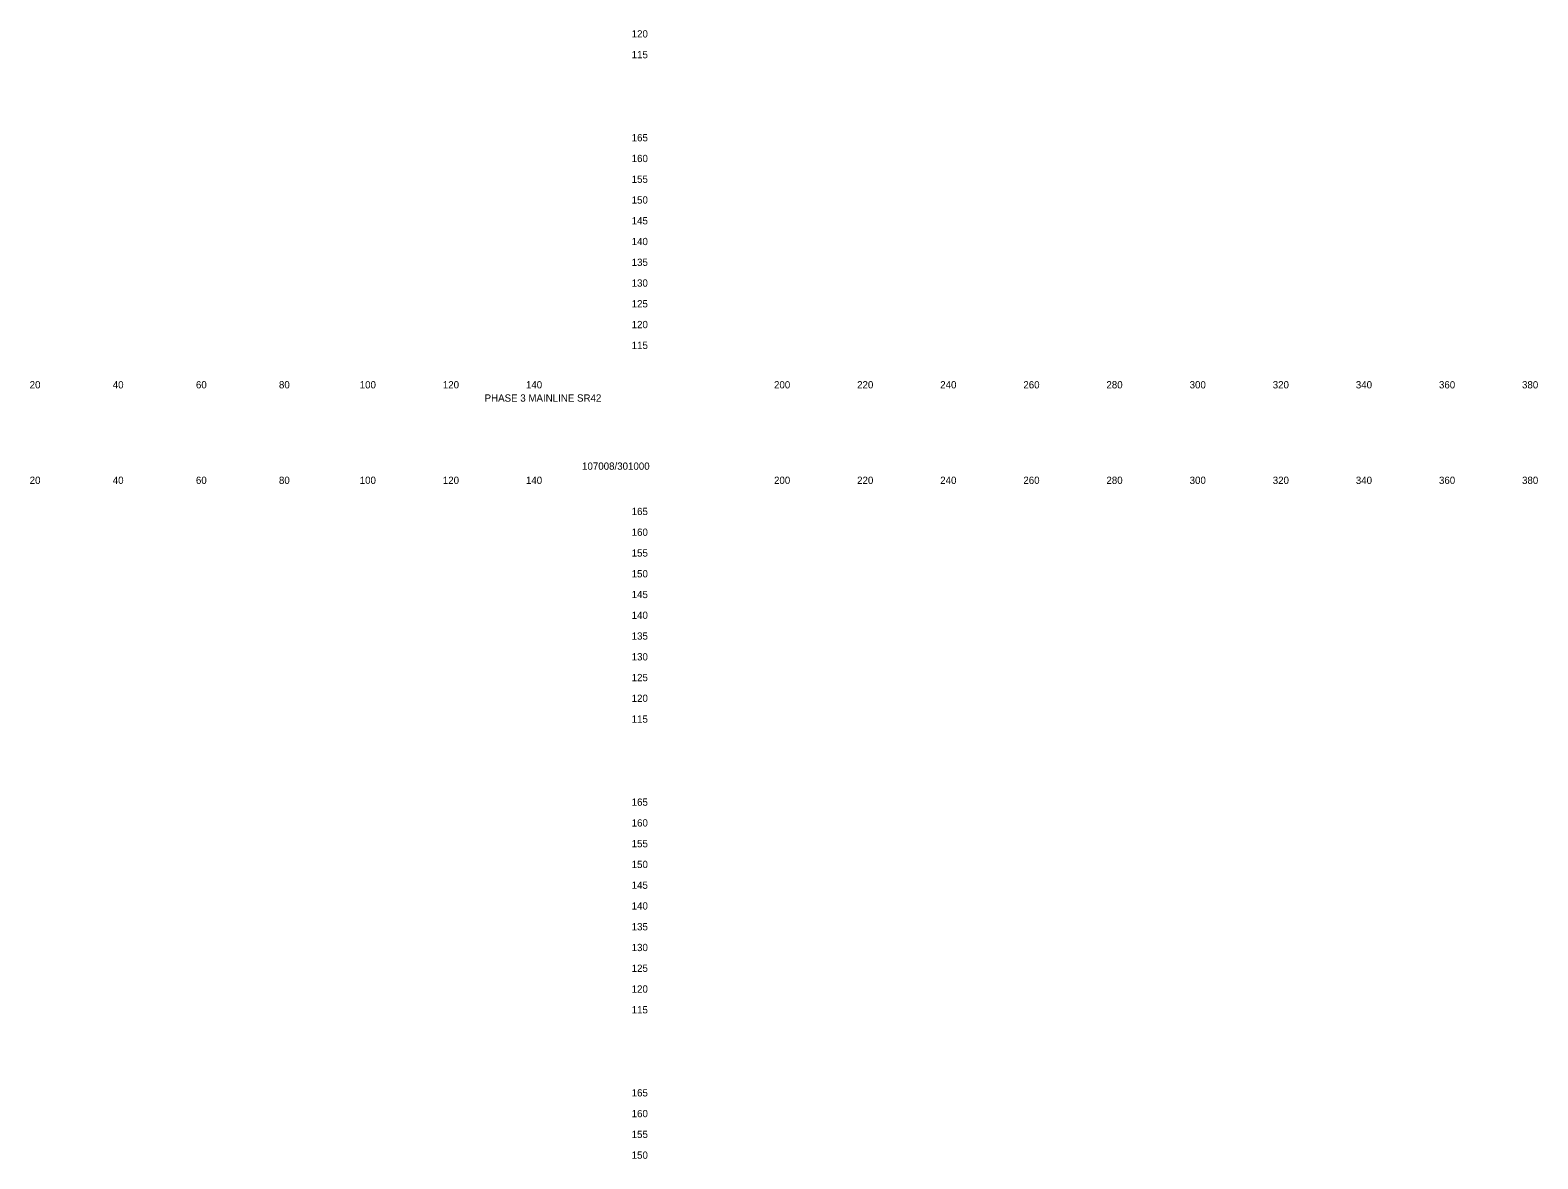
# Model space of a CAD drawing. Extents: x 21281 to 22024, y 6472 to 15198.
# Drawn here: x 21661.4 to 22024.2, y 14109.8 to 14381.6 of the extents above; entities that cross this region are included whole.
import ezdxf

# ---------------------------------------------------------------- set-up
doc = ezdxf.new("R2010")
doc.units = 0
doc.layers.add('Draft_XS_Grid', color=7, linetype='Continuous')
doc.layers.add('Draft_XS_Text', color=7, linetype='Continuous')

msp = doc.modelspace()

# ---------------------------------------------------------------- texts
at = {"layer": 'Draft_XS_Grid'}
for s, p in [('  120  ', (21804.84, 14379.84)), ('  115  ', (21804.84, 14374.84)), ('  165  ', (21804.84, 14354.84)), ('  160  ', (21804.84, 14349.84)), ('  155  ', (21804.84, 14344.84)), ('  150  ', (21804.84, 14339.84)), ('  145  ', (21804.84, 14334.84)), ('  140  ', (21804.84, 14329.84)), ('  135  ', (21804.84, 14324.84)), ('  130  ', (21804.84, 14319.84)), ('  125  ', (21804.84, 14314.84)), ('  120  ', (21804.84, 14309.84)), ('  115  ', (21804.84, 14304.84)), ('  165  ', (21804.84, 14264.84)), ('  160  ', (21804.84, 14259.84)), ('  155  ', (21804.84, 14254.84)), ('  150  ', (21804.84, 14249.84)), ('  145  ', (21804.84, 14244.84)), ('  140  ', (21804.84, 14239.84)), ('  135  ', (21804.84, 14234.84)), ('  130  ', (21804.84, 14229.84)), ('  125  ', (21804.84, 14224.84)), ('  120  ', (21804.84, 14219.84)), ('  115  ', (21804.84, 14214.84)), ('  165  ', (21804.84, 14194.84)), ('  160  ', (21804.84, 14189.84)), ('  155  ', (21804.84, 14184.84)), ('  150  ', (21804.84, 14179.84)), ('  145  ', (21804.84, 14174.84)), ('  140  ', (21804.84, 14169.84)), ('  135  ', (21804.84, 14164.84)), ('  130  ', (21804.84, 14159.84)), ('  125  ', (21804.84, 14154.84)), ('  120  ', (21804.84, 14149.84)), ('  115  ', (21804.84, 14144.84)), ('  165  ', (21804.84, 14124.84)), ('  160  ', (21804.84, 14119.84)), ('  155  ', (21804.84, 14114.84)), ('  150  ', (21804.84, 14109.84))]:
    msp.add_text(s, height=1.75, dxfattribs=at).set_placement(p)
at = {"layer": 'Draft_XS_Text'}
for s, p in [('  20  ', (21659.95, 14295.34)), ('  40  ', (21679.95, 14295.34)), ('  60  ', (21699.97, 14295.34)), ('  80  ', (21719.95, 14295.34)), ('  100  ', (21739.39, 14295.34)), ('  120  ', (21759.39, 14295.34)), ('  140  ', (21779.39, 14295.34)), ('  200  ', (21839.1, 14295.34)), ('  220  ', (21859.1, 14295.34)), ('  240  ', (21879.1, 14295.34)), ('  260  ', (21899.11, 14295.34)), ('  280  ', (21919.1, 14295.34)), ('  300  ', (21939.13, 14295.34)), ('  320  ', (21959.13, 14295.34)), ('  340  ', (21979.13, 14295.34)), ('  360  ', (21999.14, 14295.34)), ('  380  ', (22019.13, 14295.34)), ('PHASE 3 MAINLINE SR42', (21770.75, 14292.15)), ('107008/301000', (21794.2, 14275.75)), ('  20  ', (21659.95, 14272.34)), ('  40  ', (21679.95, 14272.34)), ('  60  ', (21699.97, 14272.34)), ('  80  ', (21719.95, 14272.34)), ('  100  ', (21739.39, 14272.34)), ('  120  ', (21759.39, 14272.34)), ('  140  ', (21779.39, 14272.34)), ('  200  ', (21839.1, 14272.34)), ('  220  ', (21859.1, 14272.34)), ('  240  ', (21879.1, 14272.34)), ('  260  ', (21899.11, 14272.34)), ('  280  ', (21919.1, 14272.34)), ('  300  ', (21939.13, 14272.34)), ('  320  ', (21959.13, 14272.34)), ('  340  ', (21979.13, 14272.34)), ('  360  ', (21999.14, 14272.34)), ('  380  ', (22019.13, 14272.34))]:
    msp.add_text(s, height=1.75, dxfattribs=at).set_placement(p)

doc.saveas('drawing.dxf')
